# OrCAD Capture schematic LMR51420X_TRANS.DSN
size D; title: LMR51420X SIMPLE SWITCHER® 4.5-V to 36-V, 2-A,; rev: 1.0; note: Datasheet: SLUSEF6B     EVM: SLUUCG9; note: Synchronous Buck Converter in a / SOT-23 Package
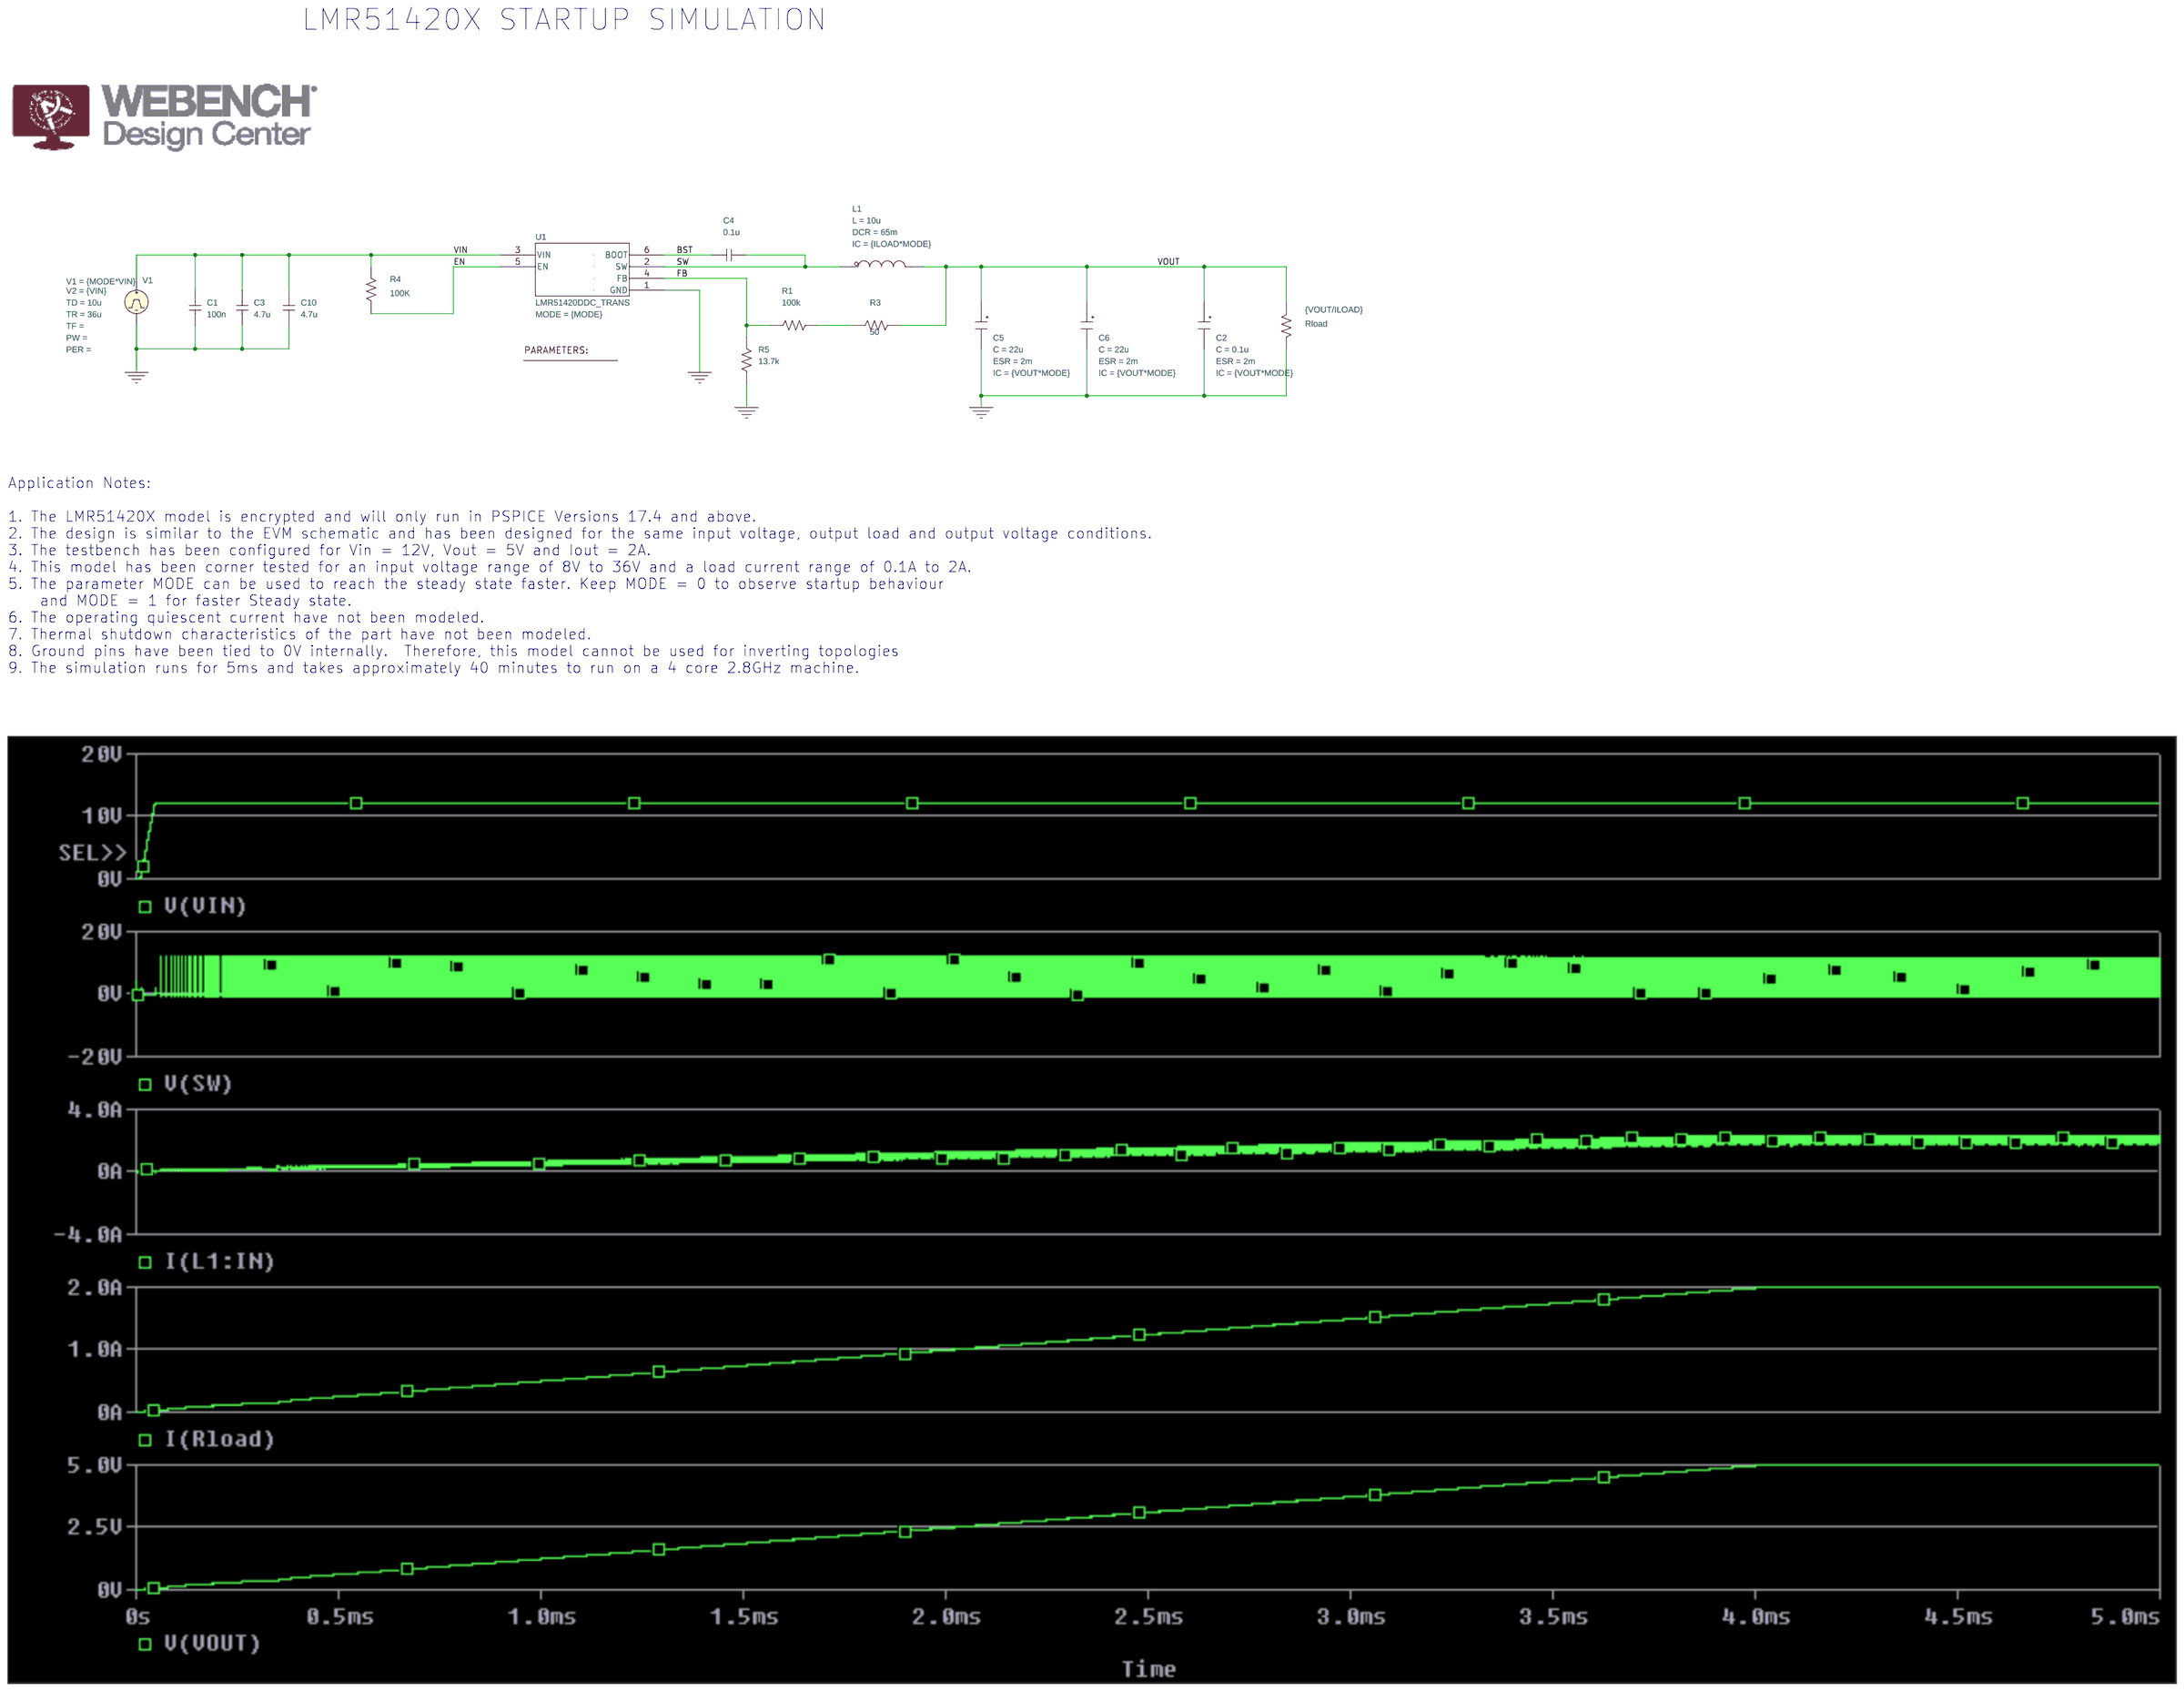
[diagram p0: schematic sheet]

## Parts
1  PARAM
C1  100n  [RAD/CK05]
C2  CESR
C3  4.7u  [RAD/CK05]
C4  0.1u  [RAD/CK05]
C5  CESR
C6  CESR
C10  4.7u  [RAD/CK05]
L1  LDCR
R1  100k  [RC05]
R3  50  [AX/RC05]
R4  100K  [AX/RC05]
R5  13.7k  [RC05]
Rload  {VOUT/ILOAD}  [AX/RC05]
U1  LMR51420DDC_TRANS  [DDC0006A-IPC_A]
V1  VPULSE

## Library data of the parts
1 = PARAM: ILOAD: 2; MODE: 0; VIN: 12; VOUT: 5
C1 C3 C10 = C
C2 = CESR_0: C: 0.1u; ESR: 2m; IC: {VOUT*MODE}; PSpiceTemplate: X^@REFDES %IN %OUT @MODEL PARAMS:  ?C|C=@C||C=100u|  ?ESR|ESR=@ESR||ESR=0.01| ?X|X=@X||X=2|  ?IC|IC=@IC||IC=2|; X: 1
C4 = C: IC: -3.3
C5 C6 = CESR_0: C: 22u; ESR: 2m; IC: {VOUT*MODE}; PSpiceTemplate: X^@REFDES %IN %OUT @MODEL PARAMS:  ?C|C=@C||C=100u|  ?ESR|ESR=@ESR||ESR=0.01| ?X|X=@X||X=2|  ?IC|IC=@IC||IC=2|; X: 1
L1 = LDCR_0: DCR: 65m; IC: {ILOAD*MODE}; L: 10u; PSpiceTemplate: X^@REFDES %IN %OUT @MODEL PARAMS:  ?L|L=@L||L=1u|  ?DCR|DCR=@DCR||DCR=0.01| ?IC|IC=@IC||IC=0|
R1 R3-R5 Rload = R
U1 = LMR51420DDC_TRANS: MODE: {MODE}
V1 = VPULSE: TD: 10u; TR: 36u; V1: {MODE*VIN}; V2: {VIN}

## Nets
VIN: C1.2 C3.2 C10.2 R4.2 U1.3(VIN) V1.1(+)
0: C1.1 C2.3(OUT) C3.1 C5.3(OUT) C6.3(OUT) C10.1 R5.1 Rload.2 U1.1(GND) V1.2(-)
BST: C4.1 U1.6(BOOT)
EN: R4.1 U1.5(EN)
FB: R1.1 R5.2 U1.4(FB)
SW: C4.2 L1.1(IN) U1.2(SW)
VOUT: C2.1(IN) C5.1(IN) C6.1(IN) L1.3(OUT) R3.2 Rload.1
N16770335: R1.2 R3.1

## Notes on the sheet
- LMR51420X STARTUP SIMULATION
- Application Notes:
  1. The LMR51420X model is encrypted and will only run in PSPICE Versions 17.4 and above.
  2. The design is similar to the EVM schematic and has been designed for the same input voltage, output load and output voltage conditions.
  3. The testbench has been configured for Vin = 12V, Vout = 5V and Iout = 2A.
  4. This model has been corner tested for an input voltage range of 8V to 36V and a load current range of 0.1A to 2A.
  5. The parameter MODE can be used to reach the steady state faster. Keep MODE = 0 to observe startup behaviour
      and MODE = 1 for faster Steady state.
  6. The operating quiescent current have not been modeled.
  7. Thermal shutdown characteristics of the part have not been modeled.
  8. Ground pins have been tied to 0V internally.  Therefore, this model cannot be used for inverting topologies
  9. The simulation runs for 5ms and takes approximately 40 minutes to run on a 4 core 2.8GHz machine.
